Omron CX-Programmer project NewProject (CX-Programmer 9.34)

# PLC GocatorTest: CJ2H CPU64-EIP
I/O table (CPU CJ2H-CPU64-EIP): rack 0 slot 11 CJ2B-EIP21

## Program Gocator (cyclic task 0)

### Section Start_and_Poll

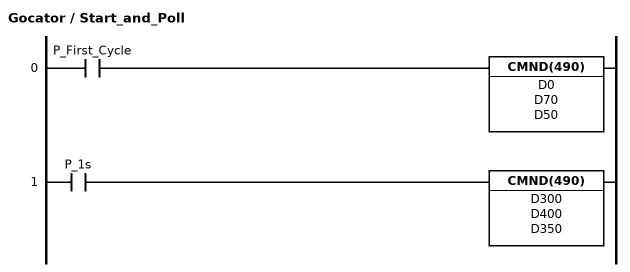
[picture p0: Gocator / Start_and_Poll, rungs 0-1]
; rung 0
LD P_First_Cycle
CMND(490) D0 D70 D50
; rung 1
LD P_1s
CMND(490) D300 D400 D350

### Section END
; rung 0
END(001)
